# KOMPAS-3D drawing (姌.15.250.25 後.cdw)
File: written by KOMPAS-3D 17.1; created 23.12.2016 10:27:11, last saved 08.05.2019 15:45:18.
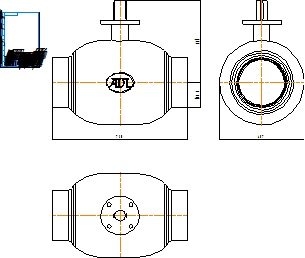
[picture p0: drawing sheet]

Sheet 1: A4, portrait

Title block, sheet 1: name: КШ.15.250.25 сс; material: Внимание! Данный продукт является объектом авторского права ООО «Торговый Дом АДЛ». / Запрещается изменение, копирование, распространение / (в том числе путем копирования на другие сайты и ресурсы в Интернете) / или любое иное использование информации и объектов без предварительного / согласия правообладателя (ООО «Торговый Дом АДЛ»).; sheets: 1; organisation: ООО "Торговый дом АДЛ"; sheet format: A4; stored path: C:\Users\tra\Desktop\2д чертежи\Шаровые краны БИВАЛ\КШ_Бивал_серия_14_15\KOMPAS_2D\КШ.15.250.25 сс.cdw

Views: Вид 1, Проекционный вид 2, Проекционный вид 3
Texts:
  Klimkovich
  ADL
Dimensions and other numbers on the sheet: 730; 441; 136,5; 457; 1:1; 1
